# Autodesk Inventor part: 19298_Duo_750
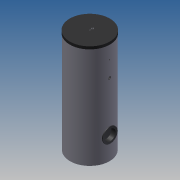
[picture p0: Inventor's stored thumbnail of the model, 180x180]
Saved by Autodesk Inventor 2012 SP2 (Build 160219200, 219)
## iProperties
allow_slope_adjustment: 0 ul
connection_type: 13 ul
flow_configuration2: 1 ul
flow_direction: 2 ul
loss_method: 0 ul
radius: 9,500 mm
radius: 22,625 mm
radius: 19,625 mm
radius: 12,250 mm
description: 0:0:19298_Duo_750
manufacturer: 0:0:Flamco Group
model: 0:0:Duo 750
url: 0:0:www.flamcogroup.com
Created: 2014-05
Part Number: 19298_Duo_750
Material: Default
Document SubType Name: Modeling
Designer: michel
Density: 1 g/cm^3
radius: 18,295 mm
Author: michel
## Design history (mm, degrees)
sketch "Sketch1"
  geometry: C1 r 375 at (0, 0); 1 further point
  constraints: 1 centre point, 1 coincident
  dimensions: "d0" = 750 diameter of C1
extrude "Extrusion1" new body sketch "Sketch1" distance "d1" = 1970; taper "d2" = 0 deg
sketch "Sketch2"
  geometry: L1 (-375, 1970)-(375, 1970) reference; L2 (-375, 0)-(375, 0) reference; L3 (375, 0)-(375, 1970) reference; L4 (375, 1970)-(380, 1970); L5 (380, 1970)-(380, 1920); L6 (380, 1920)-(375, 1920); L7 (375, 1920)-(375, 1970); L8 (0, -366)-(0, 2196) reference; 1 further point
  constraints: 8 end point, 2 parallel, 1 horizontal, 1 perpendicular
  dimensions: "d3" = 5 distance of L5.end L6.end; "d4" = 50 distance of L4.end L5.end
revolve "Revolution1" sketch "Sketch2" stored, may be unused: angle "d5" = 90 deg
workplane "Work Plane1"
workplane "Work Plane2"
workplane "Work Plane3"
workplane "Work Plane4"
workplane "Work Plane5"
workplane "Work Plane6"
workplane "Work Plane11"
workplane "Work Plane12"
sketch "Sketch3"
  geometry: L1 (526.398, 1880)-(-525.233, 1880) reference; L2 (526.398, 1040)-(-525.233, 1040) reference; L3 (526.398, 890)-(-525.233, 890) reference; L4 (526.398, 320)-(-525.233, 320) reference; L5 (526.398, 60)-(-525.233, 60) reference; L6 (375, 0)-(375, 1920) reference; L7 (375, 1880)-(335, 1880); L8 (335, 1880)-(335, 1900.955); L9 (335, 1900.955)-(375, 1900.955); L10 (375, 1900.955)-(375, 1880); L11 (375, 1040)-(335, 1040); L12 (335, 1040)-(335, 1060.955); L13 (335, 1060.955)-(375, 1060.955); L14 (375, 1060.955)-(375, 1040); L15 (335, 1861.705)-(335, 1859.045); L16 (335, 1859.045)-(376, 1859.045); L17 (376, 1859.045)-(376, 1861.705); L18 (376, 1861.705)-(335, 1861.705); L19 (335, 890)-(335, 903.22); L20 (375, 890)-(335, 890); L21 (335, 903.22)-(375, 903.22); L22 (375, 903.22)-(375, 890); L23 (335, 877.75)-(335, 876.78); L24 (335, 876.78)-(376, 876.78); L25 (376, 876.78)-(376, 877.75); L26 (376, 877.75)-(335, 877.75); L27 (335.165, 340.955)-(375.165, 340.955); L28 (335.165, 320)-(335.165, 340.955); L29 (375.165, 320)-(335.165, 320); L30 (375.165, 340.955)-(375.165, 320); L31 (376.165, 300.375)-(335.165, 300.375); L32 (335.165, 300.375)-(335.165, 299.045); L33 (335.165, 299.045)-(376.165, 299.045); L34 (376.165, 299.045)-(376.165, 300.375); L35 (335, 80.955)-(375, 80.955); L36 (335, 60)-(335, 80.955); L37 (375, 60)-(335, 60); L38 (375, 80.955)-(375, 60); L39 (376, 40.375)-(335, 40.375); L40 (335, 40.375)-(335, 39.045); L41 (335, 39.045)-(376, 39.045); L42 (376, 39.045)-(376, 40.375); L43 (335, 1019.045)-(375, 1019.045); L44 (335, 1020.375)-(335, 1019.045); L45 (375, 1019.045)-(376, 1019.045); L46 (376, 1019.045)-(376, 1020.375); L47 (376, 1020.375)-(335, 1020.375); L48 (-541, 1670)-(533.5, 1670) reference; L49 (-541, 1370)-(533.5, 1370) reference; L50 (-375, 0)-(-375, 1920) reference; L51 (-375, 1670)-(-335, 1670); L52 (-335, 1670)-(-335, 1680.475); L53 (-335, 1680.475)-(-375, 1680.475); L54 (-375, 1680.475)-(-375, 1670); L55 (-376, 1659.525)-(-335, 1659.525); L56 (-335, 1659.525)-(-335, 1660.5); L57 (-335, 1660.5)-(-376, 1660.5); L58 (-376, 1660.5)-(-376, 1659.525); L59 (-375, 1370)-(-335, 1370); L60 (-335, 1370)-(-335, 1393.9); L61 (-335, 1393.9)-(-375, 1393.9); L62 (-375, 1393.9)-(-375, 1370); L63 (-376, 1346.1)-(-335, 1346.1); L64 (-335, 1346.1)-(-335, 1347.375)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; 2 further points
  constraints: 114 end point, 17 parallel, 8 horizontal, 7 perpendicular, 6 point on line
  dimensions: "d19" = 40 distance of L8.end L9.end; "d21" = 40 distance of L12.end L13.end; "d70" = 20.955 distance between parallel lines of L1 L9; "d73" = 40 distance of L19.end L21.end; "d74" = 40 distance of L27.start L27.end; "d75" = 40 distance of L35.start L35.end; "d76" = 13.22 distance between parallel lines of L3 L21; "d85" = 20.955 distance between parallel lines of L2 L13; "d108" = 20.955 distance between parallel lines of L1 L16 (= d70); "d109" = 2.66 distance between parallel lines of L18 L16 (computed from d70); "d110" = 20.955 distance between parallel lines of L11 L13 (= d85); "d111" = 20.955 distance between parallel lines of L2 L43 (= d85); "d112" = 1.33 distance between parallel lines of L47 L43 (computed from d85); "d113" = 13.22 distance between parallel lines of L20 L21 (= d76); "d114" = 13.22 distance between parallel lines of L24 L3 (= d76); "d115" = 0.97 distance between parallel lines of L26 L24 (computed from d76); "d116" = 20.955 distance between parallel lines of L4 L27; "d117" = 20.955 distance of L27.start L28.start (= d116); "d118" = 20.955 distance between parallel lines of L33 L4 (= d116); "d119" = 1.33 distance between parallel lines of L31 L33 (computed from d116); "d120" = 20.955 distance from line of L35 L36.start (= d121); "d121" = 20.955 distance between parallel lines of L5 L35; "d122" = 20.955 distance between parallel lines of L41 L5 (= d121); "d123" = 1.33 distance between parallel lines of L39 L41 (computed from d121); "d129" = 40 distance of L53.end L52.end; "d130" = 10.475 distance of L52.end L51.end; "d131" = 10.475 distance between parallel lines of L48 L55; "d132" = 0.975 distance between parallel lines of L57 L55; "d134" = 23.9 distance between parallel lines of L49 L61; "d135" = 23.9 distance between parallel lines of L49 L63; "d136" = 1.275 distance between parallel lines of L65 L63
revolve "Revolution2" stored, may be unused: angle "d23" = 90 deg
sketch "Sketch5"
  geometry: L1 (-375, 0)-(-375, 1920) reference; L2 (-375, 0)-(-375, 435); L3 (-220, 435)-(-594, 435); L4 (-375, 435)-(-387.5, 435); L5 (-387.5, 435)-(-387.5, 575); L6 (-387.5, 575)-(-375, 575); L7 (-375, 575)-(-375, 435); L8 (-375, 0)-(375, 0) reference; 1 further point
  constraints: 12 end point, 2 parallel, 2 perpendicular, 1 horizontal, 1 point on line
  dimensions: "d35" = 435 distance of L1.start L2.end; "d36" = 12.5 distance of L5.end L6.end; "d37" = 140 distance of L4.end L5.end; "d124" = 435 distance between parallel lines of L8 L3 (= d35)
revolve "Revolution7" sketch "Sketch5" stored, may be unused: angle "d38" = 90 deg
sketch "Sketch6"
  geometry: C1 r 122.5 at (0, 0); A1 r 140 centre (0, 0) between (140, 0) and (-140, 0) reference; 1 further point
  constraints: 1 centre point, 1 coincident
  dimensions: "d39" = 245 diameter of C1
extrude "Extrusion3" join sketch "Sketch6" stored distance "d40" = 40; taper "d41" = 0 deg
sketch "Sketch7"
  geometry: C1 r 140 at (0, 0) reference; C2 r 102.5 at (0, 0); 1 further point
  constraints: 1 centre point, 1 coincident
  dimensions: "d42" = 205 diameter of C2
extrude "Extrusion4" cut sketch "Sketch7" distance "d43" = 80; taper "d44" = 0 deg
sketch "Sketch15"
  geometry: L1 (-533.5, 0)-(541, 0) reference; C1 r 20.955 at (0, 50); C2 r 380 at (0, 0) reference; C3 r 10.475 at (0, 0); C4 r 19.625 at (0, 50); C5 r 9.5 at (0, 0)
  constraints: 4 centre point, 3 coincident
  dimensions: "d142" = 41.91 diameter of C1; "d143" = 50 distance from line of L1 C1.centre; "d144" = 20.95 diameter of C3; "d145" = 39.25 diameter of C4; "d146" = 19 diameter of C5
revolve "Revolution9" stored, may be unused: angle "d69" = 90 deg
revolve "Revolution10" stored, may be unused: angle "d92" = 90 deg
revolve "Revolution11" stored, may be unused: angle "d93" = 90 deg
revolve "Revolution12" stored, may be unused: angle "d94" = 90 deg
revolve "Revolution13" stored, may be unused: angle "d95" = 90 deg
revolve "Revolution14" stored, may be unused: angle "d96" = 90 deg
revolve "Revolution15" stored, may be unused: angle "d97" = 90 deg
revolve "Revolution16" stored, may be unused: angle "d98" = 90 deg
revolve "Revolution17" stored, may be unused: angle "d99" = 90 deg
revolve "Revolution18" stored, may be unused: angle "d138" = 90 deg
revolve "Revolution19" stored, may be unused: angle "d139" = 90 deg
revolve "Revolution20" stored, may be unused: angle "d140" = 90 deg
revolve "Revolution21" stored, may be unused: angle "d141" = 90 deg
extrude "Extrusion11" cut sketch "Sketch15" distance "d147" = 40; taper "d148" = 0 deg
extrude "Extrusion12" join sketch "Sketch15" distance "d149" = 2; taper "d150" = 0 deg
body "Solid1"
node "Projected Loop1"
other parameters: "d12" = 0
